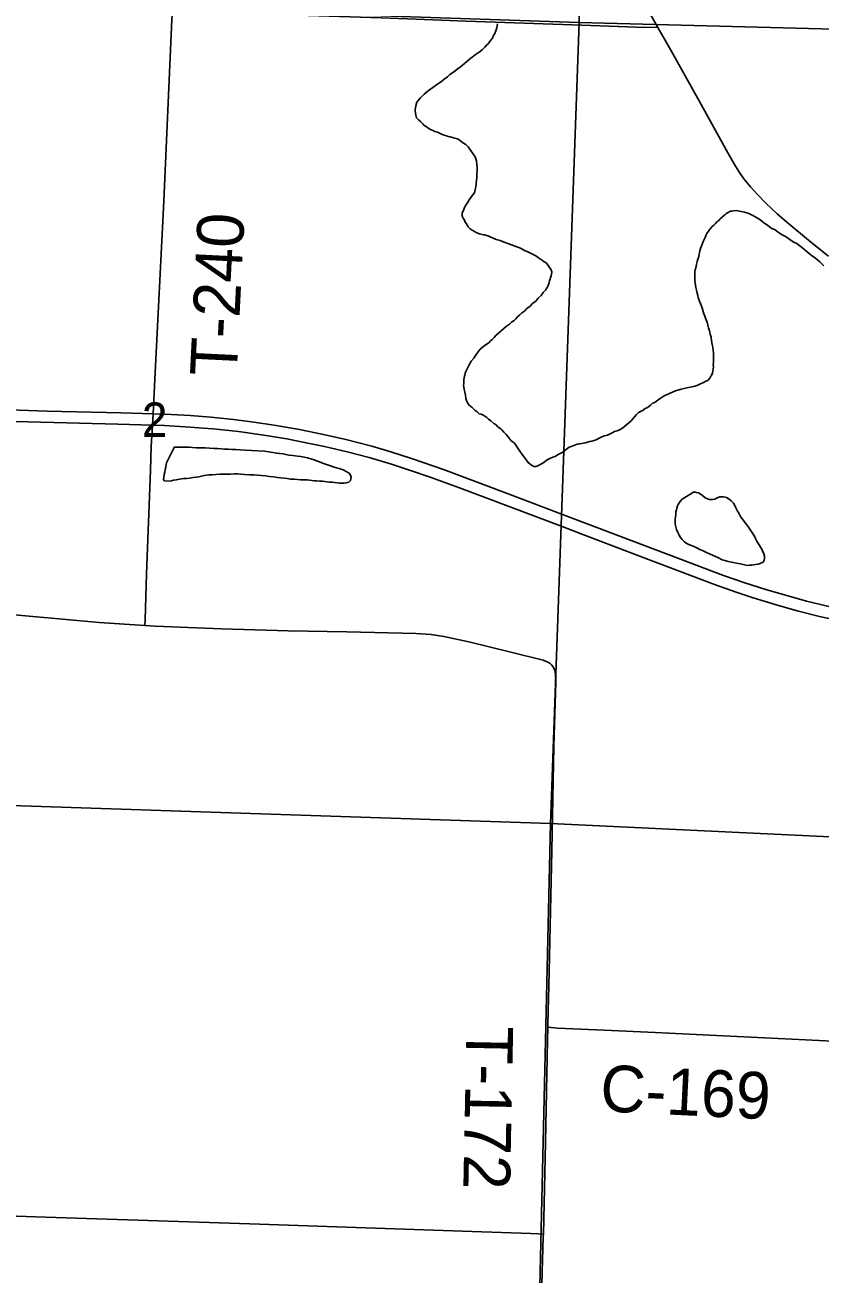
# Model space of a CAD drawing. Extents: x 1587405 to 1714697, y 1028970 to 1155083.
# Drawn here: x 1673654 to 1678758, y 1083782 to 1091803 of the extents above; entities that cross this region are included whole.
import ezdxf

# ---------------------------------------------------------------- set-up
doc = ezdxf.new("R2010")
doc.units = 0
for name, color, linetype in [('GM_X_County_Road', 7, 'Continuous'), ('GM_X_County_Road_Text', 7, 'Continuous'), ('GM_X_Major_River', 7, 'Continuous'), ('GM_X_Minor_Lake', 7, 'Continuous'), ('GM_X_Section', 7, 'Continuous'), ('GM_X_Section_Text', 7, 'Continuous'), ('GM_X_State_Route', 7, 'Continuous'), ('GM_X_Township_Road', 7, 'Continuous'), ('GM_X_Township_Road_Text', 7, 'Continuous')]:
    doc.layers.add(name, color=color, linetype=linetype)

msp = doc.modelspace()

# ---------------------------------------------------------------- linework, layer by layer
at = {"layer": 'GM_X_County_Road'}
for points in [[(1671816.4, 1088190.1), (1672254.1, 1088147.3), (1673442.9, 1088026.9), (1674129.6, 1087966.5), (1674423.7, 1087946.6)], [(1674423.7, 1087946.6), (1674489.9, 1087942.2), (1674916.2, 1087925), (1675342.7, 1087911.9), (1675720.2, 1087905.4), (1676163.2, 1087894.9), (1676261.3, 1087887.6), (1676342.4, 1087875.8), (1676503, 1087841.8), (1676773.7, 1087774.2), (1676981.2, 1087723.3), (1677011.7, 1087711.3), (1677025.5, 1087702.4), (1677037.2, 1087691.2), (1677047.1, 1087676.9)], [(1677047.1, 1087676.9), (1677055.6, 1087657.4), (1677060.5, 1087632.1), (1677061.3, 1087582.4), (1677049.9, 1087172.2), (1677035.5, 1086499.5), (1677017.7, 1085629.8), (1677010.8, 1085390.8), (1677010.5, 1085366.6)], [(1677010.5, 1085366.6), (1677071.8, 1085361.7), (1677372.9, 1085348.5), (1677700.7, 1085332.1), (1679192.3, 1085259.5), (1679602, 1085237.6), (1679667.6, 1085239.4), (1679716.3, 1085246.2), (1679764, 1085257.9), (1679872.5, 1085295.6), (1681290.5, 1085822)]]:
    msp.add_lwpolyline(points, dxfattribs=at)
at = {"layer": 'GM_X_Major_River'}
for points in [[(1676397.8, 1091081), (1676383.7, 1091085), (1676371.7, 1091087.1), (1676359.6, 1091091.1), (1676345.6, 1091095.2), (1676327.6, 1091101.3), (1676315.5, 1091107.3), (1676301.5, 1091113.4), (1676285.5, 1091119.5), (1676267.4, 1091127.6), (1676253.4, 1091133.6), (1676239.4, 1091141.7), (1676229.3, 1091149.8), (1676217.3, 1091157.8), (1676207.3, 1091167.9), (1676195.3, 1091180), (1676179.3, 1091194.1), (1676167.2, 1091206.1), (1676163.3, 1091224.2), (1676161.3, 1091238.3), (1676159.3, 1091250.3), (1676159.3, 1091260.3), (1676161.4, 1091270.4), (1676163.4, 1091284.4), (1676169.5, 1091306.5), (1676179.5, 1091320.5), (1676191.6, 1091332.5), (1676203.7, 1091346.5), (1676217.8, 1091358.5), (1676231.9, 1091370.5), (1676250, 1091386.5), (1676272.1, 1091400.4), (1676296.2, 1091418.4), (1676314.3, 1091430.4), (1676330.4, 1091442.4), (1676344.4, 1091454.4), (1676366.5, 1091470.4), (1676382.6, 1091484.3), (1676404.7, 1091500.3), (1676428.9, 1091518.3), (1676451, 1091534.3), (1676515.3, 1091590.3), (1676543.5, 1091610.2), (1676569.6, 1091628.2), (1676589.7, 1091644.2), (1676605.8, 1091660.2), (1676619.9, 1091674.2), (1676630, 1091684.2), (1676636, 1091694.2), (1676644.1, 1091704.2), (1676656.1, 1091718.2), (1676662.2, 1091734.3), (1676668.2, 1091744.3), (1676676.3, 1091764.3), (1676682.4, 1091784.4), (1676686.4, 1091798.4), (1676688.5, 1091810.4)], [(1676508.8, 1089623.8), (1676518.9, 1089643.8), (1676535, 1089663.9), (1676551.1, 1089685.9), (1676577.2, 1089719.9), (1676599.4, 1089739.9), (1676615.4, 1089749.9), (1676631.5, 1089761.9), (1676643.6, 1089773.9), (1676653.7, 1089783.9), (1676665.7, 1089795.9), (1676679.8, 1089811.9), (1676695.9, 1089825.9), (1676746.2, 1089867.8), (1676764.3, 1089881.8), (1676778.3, 1089893.8), (1676794.4, 1089905.8), (1676804.5, 1089915.8), (1676816.5, 1089927.8), (1676830.6, 1089941.8), (1676842.7, 1089951.8), (1676854.8, 1089959.8), (1676864.8, 1089969.8), (1676876.9, 1089981.8), (1676897, 1089997.8), (1676913.1, 1090013.8), (1676933.2, 1090029.8), (1676949.3, 1090047.8), (1676967.4, 1090065.8), (1676981.5, 1090083.8), (1676995.6, 1090099.8), (1677005.7, 1090117.8), (1677013.7, 1090129.8), (1677019.8, 1090147.9), (1677021.8, 1090159.9), (1677025.8, 1090169.9), (1677027.9, 1090182), (1677031.9, 1090192), (1677033.9, 1090202), (1677036, 1090218.1), (1677030, 1090234.1), (1677022, 1090246.2), (1677008, 1090264.3), (1677000, 1090274.4), (1676988, 1090282.4), (1676976, 1090290.5), (1676963.9, 1090298.6), (1676949.9, 1090306.6), (1676933.9, 1090320.7), (1676907.8, 1090332.8), (1676885.8, 1090343), (1676861.7, 1090355.1), (1676835.6, 1090369.2), (1676753.4, 1090399.6), (1676729.4, 1090407.7), (1676705.3, 1090417.8), (1676679.2, 1090425.9), (1676655.2, 1090436), (1676625.1, 1090448.1), (1676605, 1090454.2), (1676589, 1090458.3), (1676572.9, 1090462.4), (1676554.9, 1090468.4), (1676538.9, 1090476.5), (1676524.8, 1090484.6), (1676512.8, 1090492.7), (1676498.8, 1090506.8), (1676488.8, 1090526.8), (1676480.8, 1090536.9), (1676474.8, 1090549), (1676466.8, 1090563.1), (1676460.8, 1090575.1), (1676460.9, 1090595.2), (1676468.9, 1090613.2), (1676473, 1090625.2), (1676481, 1090639.2), (1676489.1, 1090651.3), (1676497.1, 1090665.3), (1676505.2, 1090679.3), (1676517.3, 1090695.3), (1676527.4, 1090709.3), (1676539.4, 1090725.3), (1676543.5, 1090743.4), (1676547.6, 1090765.4), (1676549.6, 1090777.5), (1676551.6, 1090787.5), (1676553.7, 1090803.6), (1676555.7, 1090823.6), (1676555.8, 1090845.7), (1676557.8, 1090865.8), (1676557.9, 1090885.8), (1676555.9, 1090905.9), (1676551.9, 1090930), (1676544, 1090956.1), (1676500, 1091020.4), (1676484, 1091034.5), (1676465.9, 1091046.6), (1676447.9, 1091060.8), (1676429.8, 1091070.8), (1676413.8, 1091076.9), (1676397.8, 1091081)], [(1678491.6, 1090470.2), (1678469.6, 1090486.3), (1678445.5, 1090498.4), (1678421.5, 1090516.6), (1678397.4, 1090532.7), (1678371.4, 1090552.8), (1678331.3, 1090577.1), (1678301.2, 1090591.2), (1678273.2, 1090601.3), (1678219, 1090611.5), (1678202.9, 1090609.6), (1678192.9, 1090607.6), (1678182.9, 1090607.6), (1678168.8, 1090599.6), (1678156.7, 1090591.7), (1678146.7, 1090583.7), (1678132.6, 1090571.7), (1678116.5, 1090557.7), (1678108.5, 1090547.7), (1678096.4, 1090537.7), (1678086.3, 1090527.7), (1678076.3, 1090517.7), (1678066.2, 1090507.7), (1678052.1, 1090493.7), (1678042.1, 1090479.7), (1678032, 1090463.6), (1678026, 1090451.6), (1678019.9, 1090437.6), (1678013.9, 1090425.6), (1678009.8, 1090415.6), (1678005.8, 1090405.5), (1677999.7, 1090389.5), (1677991.7, 1090367.4), (1677987.6, 1090353.4), (1677981.5, 1090331.4), (1677979.5, 1090315.3), (1677973.4, 1090299.3), (1677969.4, 1090283.3), (1677965.3, 1090267.2), (1677963.3, 1090251.2), (1677957.2, 1090231.1), (1677955.2, 1090215.1), (1677955.1, 1090199), (1677955.1, 1090187), (1677955.1, 1090176.9), (1677955.1, 1090162.9), (1677961, 1090116.7), (1677964.9, 1090100.7), (1677968.9, 1090080.6), (1677972.9, 1090064.5), (1677976.9, 1090052.5), (1677982.9, 1090034.4), (1677990.8, 1090014.3), (1677996.8, 1089996.2), (1678002.8, 1089978.1), (1678010.8, 1089954), (1678018.7, 1089931.9), (1678024.7, 1089913.9), (1678032.7, 1089893.8), (1678038.7, 1089875.7), (1678042.6, 1089857.6), (1678048.6, 1089839.5), (1678052.6, 1089817.4), (1678058.6, 1089797.4), (1678062.5, 1089775.3), (1678066.5, 1089751.2), (1678070.5, 1089733.1), (1678072.4, 1089713), (1678074.4, 1089697), (1678074.3, 1089676.9), (1678074.3, 1089656.9), (1678074.2, 1089636.8), (1678072.2, 1089620.7), (1678074.2, 1089608.7), (1678072.1, 1089592.6), (1678070.1, 1089580.6), (1678068.1, 1089568.6), (1678064, 1089556.6), (1678058, 1089546.5), (1678051.9, 1089534.5), (1678037.8, 1089520.5), (1678025.8, 1089514.5), (1678009.7, 1089506.6), (1677991.6, 1089498.6), (1677973.6, 1089490.6), (1677955.5, 1089482.7), (1677937.4, 1089478.7), (1677925.4, 1089476.8), (1677903.3, 1089472.8), (1677885.2, 1089468.8), (1677867.1, 1089464.9), (1677831, 1089453), (1677814.9, 1089447), (1677796.8, 1089439), (1677776.7, 1089429.1), (1677762.7, 1089423.1), (1677750.6, 1089417.1), (1677732.5, 1089405.1), (1677720.5, 1089397.1), (1677706.4, 1089385.1), (1677692.3, 1089377.2)], [(1678782.1, 1090256.5), (1678756.1, 1090280.7), (1678730.1, 1090304.9), (1678702, 1090325), (1678676, 1090345.2), (1678649.9, 1090367.3), (1678627.9, 1090383.5), (1678609.9, 1090399.6), (1678589.8, 1090407.7), (1678573.8, 1090419.8), (1678555.7, 1090431.8), (1678535.7, 1090443.9), (1678515.7, 1090456.1), (1678491.6, 1090470.2)], [(1677692.3, 1089377.2), (1677682.3, 1089373.2), (1677670.2, 1089361.2), (1677658.1, 1089351.2), (1677646.1, 1089343.2), (1677636, 1089339.2), (1677622, 1089329.2), (1677605.9, 1089321.3), (1677593.8, 1089313.3), (1677577.7, 1089299.3), (1677569.7, 1089289.3), (1677557.6, 1089275.3), (1677543.5, 1089259.3), (1677529.5, 1089245.3), (1677519.4, 1089239.3), (1677503.3, 1089225.3), (1677489.2, 1089213.3), (1677471.2, 1089203.3), (1677455.1, 1089197.3), (1677439, 1089191.4), (1677427, 1089185.4), (1677410.9, 1089177.4), (1677392.8, 1089169.5), (1677374.7, 1089163.5), (1677356.6, 1089157.5), (1677340.6, 1089149.6), (1677324.5, 1089141.6), (1677308.4, 1089133.6), (1677292.4, 1089129.6), (1677280.3, 1089127.7), (1677266.3, 1089123.7), (1677252.2, 1089119.8), (1677240.2, 1089117.8), (1677228.1, 1089115.8), (1677216.1, 1089113.8), (1677200, 1089109.9), (1677165.9, 1089097.9), (1677147.8, 1089092), (1677129.7, 1089078), (1677119.6, 1089070), (1677107.6, 1089060), (1677093.5, 1089054), (1677077.4, 1089044.1), (1677067.4, 1089038.1), (1677057.3, 1089032.1), (1677043.3, 1089028.1), (1677023.2, 1089018.1), (1677011.1, 1089012.2), (1676999.1, 1089006.2), (1676985, 1088994.2), (1676964.9, 1088982.2), (1676946.8, 1088972.2), (1676934.7, 1088968.3), (1676920.7, 1088968.3), (1676906.7, 1088976.4), (1676896.6, 1088982.4), (1676884.6, 1088992.5), (1676874.6, 1089008.6), (1676860.6, 1089024.7), (1676846.6, 1089044.8), (1676830.6, 1089066.9), (1676814.6, 1089091.1), (1676796.6, 1089117.2), (1676772.6, 1089135.3), (1676758.6, 1089155.5), (1676742.6, 1089173.6), (1676728.5, 1089187.7), (1676716.5, 1089199.8), (1676708.5, 1089209.8), (1676698.5, 1089215.9), (1676688.5, 1089223.9), (1676678.5, 1089234), (1676664.4, 1089244.1), (1676644.4, 1089260.2), (1676630.4, 1089272.3), (1676618.4, 1089282.3), (1676600.3, 1089294.4), (1676582.3, 1089302.5), (1676570.3, 1089306.6), (1676556.2, 1089318.7), (1676544.2, 1089326.7), (1676534.2, 1089338.8), (1676522.2, 1089348.9), (1676510.2, 1089356.9), (1676496.2, 1089373), (1676488.2, 1089391.1), (1676484.2, 1089405.2), (1676482.2, 1089425.2), (1676478.3, 1089445.3), (1676474.3, 1089461.4), (1676472.3, 1089477.4), (1676470.3, 1089487.5), (1676472.4, 1089499.5), (1676472.4, 1089509.6), (1676472.4, 1089523.6), (1676474.5, 1089539.6), (1676478.5, 1089553.7), (1676480.5, 1089567.7), (1676484.6, 1089577.7), (1676494.7, 1089599.8), (1676508.8, 1089623.8)]]:
    msp.add_lwpolyline(points, dxfattribs=at)
at = {"layer": 'GM_X_Minor_Lake'}
for points in [[(1674612.9, 1089094.2), (1674562.5, 1088990.1), (1674560.5, 1088980), (1674558.4, 1088964), (1674554.4, 1088948), (1674552.3, 1088931.9), (1674548.3, 1088915.9), (1674546.2, 1088895.8), (1674542.2, 1088885.8), (1674548.2, 1088875.7), (1674580.3, 1088873.6), (1674594.3, 1088875.6), (1674608.4, 1088879.6), (1674624.5, 1088881.5), (1674646.6, 1088885.4), (1674670.6, 1088889.4), (1674692.7, 1088891.3), (1674712.8, 1088893.2), (1674732.9, 1088897.2), (1674753, 1088899.1), (1674769, 1088901.1), (1674787.1, 1088905.1), (1674805.2, 1088909), (1674833.3, 1088912.9), (1674855.4, 1088914.9), (1674879.4, 1088916.8), (1674905.5, 1088918.7), (1674927.6, 1088918.6), (1674951.7, 1088918.6), (1674973.8, 1088918.5), (1674995.9, 1088920.4), (1675017.9, 1088920.3), (1675040, 1088918.3), (1675064.1, 1088916.2), (1675096.2, 1088914.1), (1675122.3, 1088914), (1675146.4, 1088911.9), (1675172.5, 1088909.8), (1675198.5, 1088907.7), (1675224.6, 1088903.6), (1675248.7, 1088901.5), (1675274.8, 1088897.4), (1675296.9, 1088895.4), (1675316.9, 1088893.3), (1675337, 1088891.2), (1675359.1, 1088887.1), (1675383.1, 1088887.1), (1675403.2, 1088885), (1675423.3, 1088882.9), (1675443.3, 1088880.8), (1675465.4, 1088880.8), (1675481.5, 1088878.7), (1675497.5, 1088876.6), (1675511.6, 1088874.6), (1675525.6, 1088874.6), (1675543.7, 1088872.5), (1675565.7, 1088872.4), (1675591.8, 1088868.3), (1675609.9, 1088866.2), (1675625.9, 1088866.2), (1675672.1, 1088860), (1675684.1, 1088860), (1675702.2, 1088859.9), (1675716.2, 1088861.9), (1675732.3, 1088865.8), (1675744.4, 1088877.8), (1675748.4, 1088897.9), (1675744.5, 1088912), (1675734.5, 1088924), (1675720.4, 1088934.1), (1675696.4, 1088946.2), (1675684.3, 1088950.3), (1675670.3, 1088954.3), (1675654.3, 1088958.4), (1675638.2, 1088962.5), (1675622.2, 1088968.6), (1675608.1, 1088974.6), (1675590.1, 1088980.7), (1675576, 1088984.8), (1675560, 1088990.8), (1675544, 1088996.9), (1675525.9, 1089003), (1675509.9, 1089011.1), (1675489.8, 1089017.1), (1675467.7, 1089023.2), (1675445.7, 1089027.3), (1675425.6, 1089031.4), (1675403.5, 1089033.5), (1675373.4, 1089037.6), (1675349.4, 1089039.7), (1675329.3, 1089043.8), (1675311.3, 1089047.8), (1675289.2, 1089049.9), (1675269.1, 1089054), (1675245.1, 1089058.1), (1675219, 1089062.2), (1675190.9, 1089066.3), (1675108.6, 1089070.6)], [(1675108.6, 1089070.6), (1675068.5, 1089072.7), (1675036.4, 1089074.8), (1675008.3, 1089076.9), (1674982.2, 1089077), (1674958.1, 1089079.1), (1674934, 1089079.1), (1674913.9, 1089081.2), (1674889.9, 1089083.3), (1674865.8, 1089083.4), (1674837.7, 1089085.5), (1674809.6, 1089087.6), (1674775.5, 1089087.7), (1674753.4, 1089087.8), (1674729.3, 1089089.8), (1674709.2, 1089091.9), (1674693.2, 1089092), (1674679.1, 1089092), (1674667.1, 1089092.1), (1674655.1, 1089092.1), (1674643, 1089092.1), (1674620.8, 1089092.5), (1674612.9, 1089094.2)], [(1677945.9, 1088802.5), (1677883.6, 1088764.5), (1677873.5, 1088758.6), (1677857.4, 1088740.5), (1677847.3, 1088724.5), (1677843.3, 1088714.5), (1677839.3, 1088700.5), (1677837.2, 1088688.4), (1677833.2, 1088674.4), (1677833.1, 1088658.3), (1677831.1, 1088642.3), (1677829.1, 1088630.3), (1677829, 1088612.2), (1677829, 1088598.2), (1677833, 1088580.1), (1677836.9, 1088562), (1677844.9, 1088543.9), (1677852.9, 1088525.8), (1677862.9, 1088511.8), (1677872.9, 1088497.7), (1677886.9, 1088485.6), (1677898.9, 1088475.5), (1677911, 1088469.5), (1677921, 1088463.4), (1677933, 1088459.4), (1677949.1, 1088453.3), (1677967.1, 1088445.2), (1677987.2, 1088435.1), (1678007.2, 1088425), (1678029.3, 1088414.9), (1678107.4, 1088380.6), (1678129.5, 1088368.4), (1678147.5, 1088364.4), (1678169.6, 1088358.3), (1678191.7, 1088352.2), (1678211.7, 1088348.1), (1678235.8, 1088344), (1678255.9, 1088339.9), (1678273.9, 1088335.9), (1678290, 1088331.8), (1678304, 1088333.8), (1678320.1, 1088333.7), (1678332.1, 1088335.7), (1678344.2, 1088337.6), (1678360.2, 1088339.6), (1678374.3, 1088343.6), (1678392.4, 1088353.5)], [(1677945.9, 1088802.5), (1677957.9, 1088802.4), (1677965.9, 1088800.4), (1677978, 1088798.3), (1677988, 1088792.3), (1678004, 1088780.2), (1678020, 1088766.1), (1678036.1, 1088760), (1678048.1, 1088756), (1678060.2, 1088755.9), (1678070.2, 1088755.9), (1678082.2, 1088757.9), (1678098.3, 1088765.8), (1678114.4, 1088771.8), (1678128.4, 1088771.8), (1678138.5, 1088771.7), (1678148.5, 1088769.7), (1678158.5, 1088767.6), (1678174.6, 1088757.6), (1678188.6, 1088747.5), (1678202.6, 1088731.4), (1678210.6, 1088717.3), (1678214.6, 1088707.3), (1678228.6, 1088681.1), (1678234.6, 1088671.1), (1678248.6, 1088647), (1678278.6, 1088606.7), (1678288.6, 1088592.7), (1678298.6, 1088578.6), (1678308.6, 1088564.5), (1678316.6, 1088552.4), (1678324.6, 1088538.4), (1678332.6, 1088526.3), (1678340.6, 1088516.2), (1678344.6, 1088504.2), (1678352.5, 1088488.1), (1678358.5, 1088478.1), (1678368.5, 1088464), (1678376.5, 1088449.9), (1678384.5, 1088435.8), (1678388.5, 1088425.8), (1678396.5, 1088405.7), (1678402.5, 1088391.6), (1678402.5, 1088377.6), (1678400.4, 1088365.6), (1678392.4, 1088353.5), (1678374.3, 1088343.6), (1678360.2, 1088339.6), (1678344.2, 1088337.6), (1678332.1, 1088335.7), (1678320.1, 1088333.7), (1678304, 1088333.8), (1678290, 1088331.8), (1678273.9, 1088335.9), (1678255.9, 1088339.9), (1678235.8, 1088344), (1678211.7, 1088348.1), (1678191.7, 1088352.2), (1678169.6, 1088358.3), (1678147.5, 1088364.4), (1678129.5, 1088368.4), (1678107.4, 1088380.6), (1678029.3, 1088414.9), (1678007.2, 1088425), (1677987.2, 1088435.1), (1677967.1, 1088445.2), (1677949.1, 1088453.3), (1677933, 1088459.4), (1677921, 1088463.4), (1677911, 1088469.5), (1677898.9, 1088475.5), (1677886.9, 1088485.6), (1677872.9, 1088497.7), (1677862.9, 1088511.8), (1677852.9, 1088525.8), (1677844.9, 1088543.9), (1677836.9, 1088562), (1677833, 1088580.1), (1677829, 1088598.2), (1677829, 1088612.2), (1677829.1, 1088630.3), (1677831.1, 1088642.3), (1677833.1, 1088658.3), (1677833.2, 1088674.4), (1677837.2, 1088688.4), (1677839.3, 1088700.5), (1677843.3, 1088714.5), (1677847.3, 1088724.5), (1677857.4, 1088740.5), (1677873.5, 1088758.6), (1677883.6, 1088764.5), (1677945.9, 1088802.5)], [(1678392.4, 1088353.5), (1678400.4, 1088365.6), (1678402.5, 1088377.6), (1678402.5, 1088391.6), (1678396.5, 1088405.7), (1678388.5, 1088425.8), (1678384.5, 1088435.8), (1678376.5, 1088449.9), (1678368.5, 1088464), (1678358.5, 1088478.1), (1678352.5, 1088488.1), (1678344.6, 1088504.2), (1678340.6, 1088516.2), (1678332.6, 1088526.3), (1678324.6, 1088538.4), (1678316.6, 1088552.4), (1678308.6, 1088564.5), (1678298.6, 1088578.6), (1678288.6, 1088592.7), (1678278.6, 1088606.7), (1678248.6, 1088647), (1678234.6, 1088671.1), (1678228.6, 1088681.1), (1678214.6, 1088707.3), (1678210.6, 1088717.3), (1678202.6, 1088731.4), (1678188.6, 1088747.5), (1678174.6, 1088757.6), (1678158.5, 1088767.6), (1678148.5, 1088769.7), (1678138.5, 1088771.7), (1678128.4, 1088771.8), (1678114.4, 1088771.8), (1678098.3, 1088765.8), (1678082.2, 1088757.9), (1678070.2, 1088755.9), (1678060.2, 1088755.9), (1678048.1, 1088756), (1678036.1, 1088760), (1678020, 1088766.1), (1678004, 1088780.2), (1677988, 1088792.3), (1677978, 1088798.3), (1677965.9, 1088800.4), (1677957.9, 1088802.4), (1677945.9, 1088802.5)]]:
    msp.add_lwpolyline(points, dxfattribs=at)
at = {"layer": 'GM_X_Section'}
for points in [[(1682643.9, 1096958.6), (1682532.3, 1091680.4), (1677212.6, 1091818.6), (1677285.8, 1097061.7)], [(1671935.5, 1091998.3), (1677212.6, 1091818.6), (1677028.4, 1086675.5), (1671767.3, 1086851.1)], [(1677212.6, 1091818.6), (1682532.3, 1091680.4), (1682413, 1086444.5), (1682412.7, 1086418.5), (1677028.4, 1086675.5)], [(1671767.3, 1086851.1), (1677028.4, 1086675.5), (1676906.4, 1081379.7), (1671613.3, 1081549.7)], [(1677028.4, 1086675.5), (1682412.7, 1086418.5), (1682308.3, 1081094.4), (1676906.4, 1081379.7)]]:
    msp.add_lwpolyline(points, close=True, dxfattribs=at)
at = {"layer": 'GM_X_State_Route'}
for points in [[(1673312.5, 1089338.9), (1673795.5, 1089323.8), (1674271.6, 1089312.3), (1674477.2, 1089305.9), (1674550.7, 1089303.7), (1674714.9, 1089295.4), (1674846, 1089285.1), (1674993.1, 1089269.9), (1675107.2, 1089255.2), (1675253.5, 1089233.2), (1675415.4, 1089205.1), (1675560.4, 1089175.8), (1675704.6, 1089142.7), (1675879.9, 1089097.9), (1676002.1, 1089061.6), (1676142.5, 1089016.8), (1676340.9, 1088948.3), (1676790.1, 1088779.1), (1677105.1, 1088660), (1677846.4, 1088379.4), (1678137.9, 1088268.5), (1678274.9, 1088220), (1678417.1, 1088175.5), (1678544.6, 1088138.1), (1678671.5, 1088103.7), (1678815.1, 1088068.5)], [(1673509.2, 1089259.4), (1674250.4, 1089240.1), (1674472.8, 1089232.5), (1674548.8, 1089230), (1674713.4, 1089221), (1674798.1, 1089214.6), (1674862.2, 1089208.8), (1675025.6, 1089191.4), (1675187.8, 1089168.8), (1675335.2, 1089145), (1675448.9, 1089122.4), (1675576.9, 1089095.3), (1675723, 1089061.1), (1675863.2, 1089024.3), (1676007.4, 1088983), (1676129.6, 1088942.4), (1676254.9, 1088899.8), (1676444.3, 1088830), (1677102.2, 1088581.7), (1677236.2, 1088531.1), (1677640.1, 1088377.5), (1678081.7, 1088210.3), (1678219.5, 1088159.5), (1678328.5, 1088123.5), (1678469.8, 1088081.1), (1678612, 1088041.5), (1678755.1, 1088005.2), (1678882.9, 1087976)]]:
    msp.add_lwpolyline(points, dxfattribs=at)
at = {"layer": 'GM_X_Township_Road'}
for points in [[(1677717.6, 1091786.3), (1677594, 1092005.2), (1677504.3, 1092161.8), (1677395.7, 1092345.6), (1677309.4, 1092485.2), (1677286.2, 1092528.8), (1677273.7, 1092559.1), (1677268.7, 1092574.7), (1677264.9, 1092590.6), (1677262, 1092606.7), (1677259.9, 1092639.5), (1677270.8, 1093296.1), (1677272.2, 1093591.6), (1677276.8, 1093805.1), (1677278.6, 1094182.7), (1677279.1, 1094439.2)], [(1674488.3, 1089527.8), (1674545.5, 1090672.4), (1674596.7, 1091837.1), (1674601.4, 1091889.7)], [(1674601.4, 1091889.7), (1674749.5, 1091884.4), (1675131.7, 1091873.7), (1675474.2, 1091863.1), (1675940.7, 1091847.6), (1676165.2, 1091840.9), (1676485.7, 1091827.4), (1677228.8, 1091801.1)], [(1677228.8, 1091801.1), (1677579.7, 1091788.6), (1677717.6, 1091786.3)], [(1677717.6, 1091786.3), (1677799.4, 1091641.5), (1677983.8, 1091311.9), (1678165.9, 1090981.2), (1678214.6, 1090895.7), (1678241, 1090854.5), (1678269.8, 1090814.9), (1678311.2, 1090764.3), (1678354.8, 1090715.5), (1678412.1, 1090657), (1678483.6, 1090589.5), (1678545.2, 1090535.6), (1678697.7, 1090411), (1678812.6, 1090318)], [(1674477.2, 1089305.9), (1674488.3, 1089527.8)], [(1674472.8, 1089232.5), (1674477.2, 1089305.9)], [(1674459.1, 1088942.8), (1674464.9, 1089098.1), (1674472.8, 1089232.5)], [(1674423.7, 1087946.6), (1674424.8, 1087982.2), (1674434, 1088277.6), (1674459.1, 1088942.8)], [(1677010.5, 1085366.6), (1677007.6, 1085284.2), (1676994.9, 1084626.8), (1676981.9, 1084038.6)], [(1671692.9, 1084217.9), (1671817.6, 1084215.4), (1672473.8, 1084192.2), (1673113.6, 1084170.1), (1673720.5, 1084148.5), (1674311, 1084129.5), (1675097.9, 1084103.5), (1676525.1, 1084055.5), (1676902.4, 1084042), (1676951.5, 1084039.9), (1676981.9, 1084038.6)], [(1676981.9, 1084038.6), (1676981.5, 1084020.3), (1676969.7, 1083643.4), (1676937.9, 1082282.9), (1676927.4, 1081857.1), (1676907.5, 1081004.7), (1676881.8, 1080119.7), (1676843.5, 1078775.8), (1676842.4, 1078739.9)]]:
    msp.add_lwpolyline(points, dxfattribs=at)

# ---------------------------------------------------------------- texts
at = {"layer": 'GM_X_County_Road_Text'}
msp.add_text('C-169', height=300, rotation=357.24828, dxfattribs=at).set_placement((1677342.6, 1084827.2))
at = {"layer": 'GM_X_Section_Text'}
msp.add_text('2', height=221, rotation=0.00001, dxfattribs=at).set_placement((1674404.3, 1089157.9))
at = {"layer": 'GM_X_Township_Road_Text'}
for s, rotation, p in [('T-240', 87.19407, (1675012.4, 1089541.8)), ('T-172', 268.8773, (1676488.5, 1085375.5))]:
    msp.add_text(s, height=300, rotation=rotation, dxfattribs=at).set_placement(p)

doc.saveas('drawing.dxf')
